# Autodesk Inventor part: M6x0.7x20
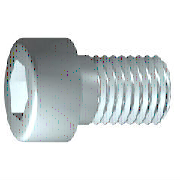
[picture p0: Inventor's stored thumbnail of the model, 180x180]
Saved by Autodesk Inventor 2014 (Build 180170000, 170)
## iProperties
Created: 2009-02
Part Number: M6x0.7x20
Material: 강, 연강
Description: 6각머리 태핑 나사
Document SubType Name: Modeling
Standard: KS B 1003
Designer: KYOUNG IL JANG
Standards Organization: KS
Language: ko-KR
Size Designation: M 6 x 20
Categories: <MemberInstance><Categories><Category DisplayName="조임쇠" InternalName="e4da775c-781d-43d5-af7c-5136215cf5a6" Mnemonic="FSTN"><Category DisplayName="볼트" InternalN
Density: 7.86 g/cm^3
Mass: 7.48273 g
Surface Area: 7.641 cm^2
Volume: 0.952002 cm^3
Vendor: CBT Solutions
Appearance: 연마 - 진회색
Company: 한국ATC센터
IsCustomPart: 1
Author: KYOUNG IL JANG
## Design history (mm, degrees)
sketch "스케치1"
  geometry: L1 (-1.333, 0)-(20, 0); L2 (20, 0)-(20, 3); L3 (20, 3)-(2.5, 3); L4 (2.5, 3)-(1.886, 3); L5 (1.886, 3)-(0, 3); L6 (0, 3)-(0, 5); L7 (0, 5)-(-6, 5); L8 (-6, 5)-(-6, 2.887); L9 (-6, 2.887)-(-3, 2.887); L10 (-3, 2.887)-(-1.333, 0); L11 (-11.2, 0)-(25.2, 0) reference; L12 (0, -1)-(0, 6) reference; L13 (2.5, 3)-(0, 3)
  constraints: 22 end point, 6 parallel, 2 collinear, 2 perpendicular, 1 horizontal, 1 point on line
  dimensions: "d1" = 17.5 distance from line of L3.end L2 (= GEL); "d2" = 0.61355 distance of L4.end L3.end (computed from GAL); "d3" = 6 distance between parallel lines of L8 L6 (= KOH); "d4" = 3 distance of L8.end L9.end (= INTI); "d5" = 60 deg angle of L10 L1; "d6" = 6 diameter of L3 L1 (= GD); "d7" = 6 diameter of L5 L1 (= BDM); "d8" = 5.7735 diameter of L9 L1 (= 1.1547 x SW); "d9" = 10 diameter of L7 L1 (= KOD); "d26" = 20 distance between parallel lines of L12 L2 (= NLG)
revolve "본체" sketch "스케치1" stored, may be unused: angle "d10" = 90 deg
sketch "스케치2"
  geometry: L1 (0, -7)-(0, 7) reference; L2 (-7, 0)-(7, 0) reference; L3 (2.887, 0)-(1.443, -2.5); L4 (1.443, -2.5)-(-1.443, -2.5); L5 (-1.443, -2.5)-(-2.887, 0); L6 (-2.887, 0)-(-1.443, 2.5); L7 (-1.443, 2.5)-(1.443, 2.5); L8 (1.443, 2.5)-(2.887, 0); 2 further points
  constraints: 12 end point, 1 coincident, 1 horizontal alignment, 1 point on line, 12 other
extrude "슬롯" join sketch "스케치2" stored distance "d11" = 10; taper "d12" = 0 deg
workplane "Work Plane1"
fillet "Fillet2" dims "d30" = 0.1 (= R)
body "Solid1"
fillet "모깎기1" dims "d17" = 0.6 (= RR)
feature "스레드" dims "d13" = 17.5 (= GEL), "d14" = 0
chamfer "모따기1" distance "d15" = 0.61345 (= -0.5 x SPD + 0.5 x GD); stored, may be unused: second distance "d16" = 0.61345 (= GUL), angle "d27" = 45 deg
other parameters: "GD" = 6 (= NND) [user parameter; used in 2 equation terms], "NLG" = 20 [user parameter; used in 1 equation term], "GEL" = 17.5 [user parameter; used in 2 equation terms], "KOD" = 10 [user parameter; used in 1 equation term], "KOH" = 6 [user parameter; used in 1 equation term], "INTI" = 3 [user parameter; used in 1 equation term], "GAL" = 0.61345 (= 0.61345 x PTC) [user parameter; used in 1 equation term], "GUL" = 0.61345 (= 0.61345 x PTC) [user parameter; used in 1 equation term], "BDM" = 6 (= NND) [user parameter; used in 1 equation term], "SW" = 5 [user parameter; used in 2 equation terms], "RR" = 0.6 [user parameter; used in 1 equation term], "SPD" = 4.7731 (= NND - 1.2269 x PTC) [user parameter; used in 1 equation term], "d19" = 0, "d28" = 0, "d29" = 0, "R" = 0.1 [user parameter; used in 1 equation term], "PHH" = 0.25 [user parameter], "GD1" = 4.7731 (= THREADDIA - 1.2269 x PTC) [user parameter], "THREADDIA" = 6 [user parameter; used in 1 equation term], "FAWI" = 45 deg [user parameter], "PTC" = 1 [user parameter; used in 5 equation terms], "NND" = 6 [user parameter; used in 3 equation terms], "TOA" = 30 deg [user parameter], "E0" = 5.775 (= 1.155 x SW) [user parameter]
